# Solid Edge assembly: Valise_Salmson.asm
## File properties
Author: Bernard DUMAS
Template: Normal.asm
Last saved by: FR026244
Revision: 46
Application: Solid Edge
Revision: a
Project Name: Slamson
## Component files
Valise_01.par
valise_02.par
Valise_03.par
Valise_04.par
Valise_10.par
Valise_05.par
Valise_06.par
rale.par
Valise_07.par
e.par
Valise_08.par
Valise_fermeture_centrale.par
Valise_11.par
Valise_09.par
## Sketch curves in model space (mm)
circle centre (475.6961, 2.0459, 61.6079) radius 22.0997
line (0, 0, 106) -> (453.5, 0, 106)
line (506.5, 0, 0) -> (425, 0, 163)
line (425, 0, 163) -> (0, 0, 163)
line (0, 0, 163) -> (0, 0, 0)
line (0, 0, 0) -> (506.5, 0, 0)
line (6, 0, 157) -> (6, 0, 6)
line (6, 0, 6) -> (496.7918, 0, 6)
line (496.7918, 0, 6) -> (421.2918, 0, 157)
line (421.2918, 0, 157) -> (6, 0, 157)
